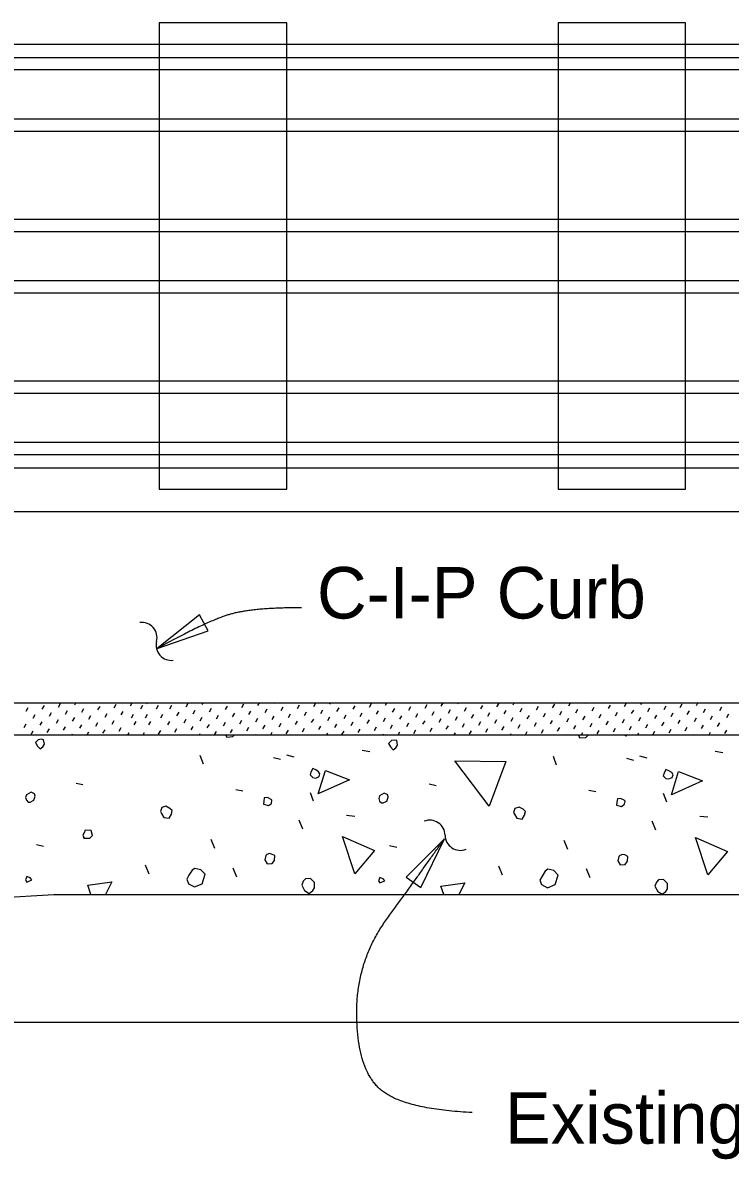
# Model space of a CAD drawing. Extents: x 1.5 to 68.7, y 0 to 31.1.
# Drawn here: x 31.375 to 34.147, y 9.197 to 13.648 of the extents above; entities that cross this region are included whole.
import ezdxf

# ---------------------------------------------------------------- set-up
doc = ezdxf.new("R2010")
doc.units = 0
for name, color, linetype in [('Dimension', 7, 'Continuous'), ('Miscellaneous', 7, 'Continuous'), ('TextStructures', 7, 'Continuous'), ('TrafBarrierConc', 7, 'Continuous')]:
    doc.layers.add(name, color=color, linetype=linetype)

msp = doc.modelspace()

# ---------------------------------------------------------------- linework, layer by layer
at = {"layer": 'Dimension'}
for points in [[(31.9014, 11.1976), (32.1009, 11.2667), (32.067, 11.3286)], [(33.0264, 10.4517), (32.8772, 10.3022), (32.9348, 10.2614)]]:
    msp.add_lwpolyline(points, close=True, dxfattribs=at)
for centre, start, end in [((31.8414, 11.2396), 345.7563, 97.4835), ((31.9569, 11.2103), 165.7563, 277.4835), ((32.9696, 10.4655), 0.5042, 112.2314), ((33.0889, 10.4666), 180.5042, 292.2314)]:
    msp.add_arc(centre, 0.0596, start, end, dxfattribs=at)
for points in [[(32.467, 11.357), (32.2731, 11.357), (32.0952, 11.3038), (31.9014, 11.1976)], [(33.1354, 9.3803), (32.866, 9.3932), (32.6865, 9.5471), (32.68, 9.9706), (32.9173, 10.2978), (33.0264, 10.4518)]]:
    msp.add_open_spline(points, degree=2, dxfattribs=at)
at = {"layer": 'Miscellaneous'}
for p, q in [((28.9195, 13.5645), (37.6978, 13.5645)), ((29.5771, 13.5123), (37.6978, 13.5123)), ((29.5783, 13.4641), (37.6978, 13.4641)), ((29.5831, 13.2713), (37.6978, 13.2713)), ((29.5842, 13.2231), (37.6978, 13.2231)), ((29.5807, 12.8791), (37.6978, 12.8791)), ((29.5795, 12.8309), (37.6978, 12.8309)), ((29.5747, 12.6381), (37.6978, 12.6381)), ((29.5735, 12.5899), (37.6978, 12.5899)), ((29.5842, 12.246), (37.6978, 12.246)), ((29.5831, 12.1978), (37.6978, 12.1978)), ((29.5783, 12.0049), (37.6978, 12.0049)), ((29.5771, 11.9567), (37.6978, 11.9567)), ((28.9195, 11.9044), (37.6978, 11.9044)), ((31.3878, 10.952), (31.3959, 10.966)), ((31.4513, 10.9601), (31.4594, 10.9741)), ((31.5148, 10.9682), (31.5229, 10.9822)), ((31.5425, 10.9405), (31.5506, 10.9545)), ((31.5783, 10.9763), (31.583, 10.9845)), ((31.606, 10.9486), (31.6141, 10.9626)), ((31.6418, 10.9844), (31.6418, 10.9845)), ((31.6695, 10.9567), (31.6776, 10.9707)), ((31.733, 10.9648), (31.7411, 10.9788)), ((31.7607, 10.9371), (31.7688, 10.9511)), ((31.7964, 10.9729), (31.8032, 10.9845)), ((31.8376, 10.9614), (31.8457, 10.9754)), ((31.8599, 10.981), (31.862, 10.9845)), ((31.8986, 10.9614), (31.9067, 10.9754)), ((31.9511, 10.9614), (31.9592, 10.9754)), ((32.0146, 10.9695), (32.0227, 10.9835)), ((32.0423, 10.9418), (32.0504, 10.9558)), ((32.0781, 10.9776), (32.0821, 10.9845)), ((32.1058, 10.9499), (32.1139, 10.9639)), ((32.1693, 10.958), (32.1774, 10.972)), ((32.2328, 10.9661), (32.2409, 10.9801)), ((32.2605, 10.9384), (32.2686, 10.9524)), ((32.2963, 10.9742), (32.3022, 10.9845)), ((32.324, 10.9465), (32.3321, 10.9605)), ((32.3598, 10.9823), (32.361, 10.9845)), ((32.3875, 10.9546), (32.3956, 10.9686)), ((32.451, 10.9627), (32.4591, 10.9767)), ((32.4787, 10.935), (32.4868, 10.949)), ((32.5145, 10.9708), (32.5224, 10.9845)), ((32.5422, 10.9431), (32.5503, 10.9571)), ((32.578, 10.9789), (32.5812, 10.9845)), ((32.6056, 10.9512), (32.6137, 10.9652)), ((32.6691, 10.9593), (32.6772, 10.9733)), ((32.7326, 10.9674), (32.7407, 10.9814)), ((32.7603, 10.9397), (32.7684, 10.9537)), ((32.7961, 10.9755), (32.8013, 10.9845)), ((32.8238, 10.9479), (32.8319, 10.9618)), ((32.8596, 10.9836), (32.8601, 10.9845)), ((32.8873, 10.956), (32.8954, 10.9699)), ((32.9508, 10.9641), (32.9589, 10.978)), ((32.9785, 10.9364), (32.9866, 10.9504)), ((33.0143, 10.9722), (33.0214, 10.9845)), ((33.042, 10.9445), (33.0501, 10.9585)), ((33.0778, 10.9803), (33.0802, 10.9845)), ((33.1055, 10.9526), (33.1136, 10.9666)), ((33.169, 10.9607), (33.1771, 10.9747)), ((33.2325, 10.9688), (33.2406, 10.9828)), ((33.2602, 10.9411), (33.2683, 10.9551)), ((33.296, 10.9769), (33.3004, 10.9845)), ((33.3237, 10.9492), (33.3318, 10.9632)), ((33.3871, 10.9573), (33.3952, 10.9713)), ((33.4506, 10.9654), (33.4587, 10.9794)), ((33.4783, 10.9377), (33.4864, 10.9517)), ((33.5141, 10.9735), (33.5205, 10.9845)), ((33.5418, 10.9458), (33.5499, 10.9598)), ((33.5776, 10.9816), (33.5793, 10.9845)), ((33.6053, 10.9539), (33.6134, 10.9679)), ((33.6688, 10.962), (33.6769, 10.976)), ((33.7323, 10.9701), (33.7404, 10.9841)), ((33.76, 10.9424), (33.7681, 10.9564)), ((33.7958, 10.9782), (33.7994, 10.9845)), ((33.8235, 10.9505), (33.8316, 10.9645)), ((33.887, 10.9586), (33.8951, 10.9726)), ((33.9505, 10.9667), (33.9586, 10.9807)), ((33.9782, 10.939), (33.9863, 10.953)), ((34.014, 10.9748), (34.0196, 10.9845)), ((34.0417, 10.9471), (34.0498, 10.9611)), ((34.0775, 10.9829), (34.0784, 10.9845)), ((34.1052, 10.9552), (34.1133, 10.9692)), ((31.4155, 10.9243), (31.4236, 10.9383)), ((31.4432, 10.8966), (31.4513, 10.9106)), ((31.479, 10.9324), (31.4871, 10.9464)), ((31.5067, 10.9047), (31.5148, 10.9187)), ((31.5702, 10.9128), (31.5783, 10.9268)), ((31.6337, 10.9209), (31.6418, 10.9349)), ((31.6614, 10.8932), (31.6695, 10.9072)), ((31.6972, 10.929), (31.7053, 10.943)), ((31.7249, 10.9013), (31.733, 10.9153)), ((31.8002, 10.9256), (31.8083, 10.9396)), ((31.8109, 10.8979), (31.8191, 10.9119)), ((31.856, 10.9256), (31.8641, 10.9396)), ((31.8681, 10.8979), (31.8762, 10.9119)), ((31.9153, 10.9256), (31.9234, 10.9396)), ((31.943, 10.8979), (31.9511, 10.9119)), ((31.9788, 10.9337), (31.9869, 10.9477)), ((32.0065, 10.906), (32.0146, 10.92)), ((32.07, 10.9141), (32.0781, 10.9281)), ((32.1335, 10.9222), (32.1416, 10.9362)), ((32.1612, 10.8945), (32.1693, 10.9085)), ((32.197, 10.9303), (32.2051, 10.9443)), ((32.2247, 10.9026), (32.2328, 10.9166)), ((32.2882, 10.9107), (32.2963, 10.9247)), ((32.3517, 10.9188), (32.3598, 10.9328)), ((32.3794, 10.8911), (32.3875, 10.9051)), ((32.4152, 10.9269), (32.4233, 10.9409)), ((32.4429, 10.8992), (32.451, 10.9132)), ((32.5064, 10.9073), (32.5145, 10.9213)), ((32.5698, 10.9154), (32.578, 10.9294)), ((32.6333, 10.9235), (32.6414, 10.9375)), ((32.661, 10.8958), (32.6691, 10.9098)), ((32.6968, 10.9316), (32.7049, 10.9456)), ((32.7245, 10.904), (32.7326, 10.9179)), ((32.788, 10.9121), (32.7961, 10.926)), ((32.8515, 10.9202), (32.8596, 10.9342)), ((32.8792, 10.8925), (32.8873, 10.9065)), ((32.915, 10.9283), (32.9231, 10.9423)), ((32.9427, 10.9006), (32.9508, 10.9146)), ((33.0062, 10.9087), (33.0143, 10.9227)), ((33.0697, 10.9168), (33.0778, 10.9308)), ((33.1332, 10.9249), (33.1413, 10.9389)), ((33.1609, 10.8972), (33.169, 10.9112)), ((33.1967, 10.933), (33.2048, 10.947)), ((33.2244, 10.9053), (33.2325, 10.9193)), ((33.2879, 10.9134), (33.296, 10.9274)), ((33.3513, 10.9215), (33.3595, 10.9355)), ((33.379, 10.8938), (33.3871, 10.9078)), ((33.4148, 10.9296), (33.4229, 10.9436)), ((33.4425, 10.9019), (33.4506, 10.9159)), ((33.506, 10.91), (33.5141, 10.924)), ((33.5695, 10.9181), (33.5776, 10.9321)), ((33.5972, 10.8904), (33.6053, 10.9044)), ((33.633, 10.9262), (33.6411, 10.9402)), ((33.6607, 10.8985), (33.6688, 10.9125)), ((33.6965, 10.9343), (33.7046, 10.9483)), ((33.7242, 10.9066), (33.7323, 10.9206)), ((33.7877, 10.9147), (33.7958, 10.9287)), ((33.8512, 10.9228), (33.8593, 10.9368)), ((33.8789, 10.8951), (33.887, 10.9091)), ((33.9147, 10.9309), (33.9228, 10.9449)), ((33.9424, 10.9032), (33.9505, 10.9172)), ((34.0059, 10.9113), (34.014, 10.9253)), ((34.0694, 10.9194), (34.0775, 10.9334)), ((34.0971, 10.8917), (34.1052, 10.9057)), ((34.1328, 10.9275), (34.141, 10.9415)), ((31.3797, 10.8885), (31.3878, 10.9025)), ((31.4074, 10.8608), (31.4155, 10.8748)), ((31.4709, 10.8689), (31.479, 10.8829)), ((31.5344, 10.877), (31.5425, 10.891)), ((31.568, 10.8595), (31.5702, 10.8633)), ((31.5979, 10.8851), (31.606, 10.8991)), ((31.6268, 10.8595), (31.6337, 10.8714)), ((31.6891, 10.8655), (31.6972, 10.8795)), ((31.7526, 10.8736), (31.7607, 10.8876)), ((31.7865, 10.8595), (31.7914, 10.868)), ((31.7881, 10.8595), (31.7883, 10.8599)), ((31.8469, 10.8595), (31.8518, 10.868)), ((31.9072, 10.8621), (31.9153, 10.8761)), ((31.9707, 10.8702), (31.9788, 10.8842)), ((32.0342, 10.8783), (32.0423, 10.8923)), ((32.067, 10.8595), (32.07, 10.8646)), ((32.0977, 10.8864), (32.1058, 10.9004)), ((32.1258, 10.8595), (32.1335, 10.8727)), ((32.1889, 10.8668), (32.197, 10.8808)), ((32.2524, 10.8749), (32.2605, 10.8889)), ((32.2872, 10.8595), (32.2882, 10.8612)), ((32.3159, 10.883), (32.324, 10.897)), ((32.346, 10.8595), (32.3517, 10.8693)), ((32.4071, 10.8634), (32.4152, 10.8774)), ((32.4706, 10.8715), (32.4787, 10.8855)), ((32.5341, 10.8796), (32.5422, 10.8936)), ((32.5661, 10.8595), (32.5698, 10.8659)), ((32.5975, 10.8877), (32.6056, 10.9017)), ((32.6252, 10.8601), (32.6333, 10.874)), ((32.6887, 10.8682), (32.6968, 10.8821)), ((32.7522, 10.8763), (32.7603, 10.8903)), ((32.7862, 10.8595), (32.788, 10.8626)), ((32.8157, 10.8844), (32.8238, 10.8984)), ((32.845, 10.8595), (32.8515, 10.8707)), ((32.9069, 10.8648), (32.915, 10.8788)), ((32.9704, 10.8729), (32.9785, 10.8869)), ((33.0339, 10.881), (33.042, 10.895)), ((33.0652, 10.8595), (33.0697, 10.8673)), ((33.0974, 10.8891), (33.1055, 10.9031)), ((33.1251, 10.8614), (33.1332, 10.8754)), ((33.1886, 10.8695), (33.1967, 10.8835)), ((33.2521, 10.8776), (33.2602, 10.8916)), ((33.2853, 10.8595), (33.2879, 10.8639)), ((33.3156, 10.8857), (33.3237, 10.8997)), ((33.3441, 10.8595), (33.3513, 10.872)), ((33.4067, 10.8661), (33.4148, 10.8801)), ((33.4702, 10.8742), (33.4783, 10.8882)), ((33.5054, 10.8595), (33.506, 10.8605)), ((33.5337, 10.8823), (33.5418, 10.8963)), ((33.5642, 10.8595), (33.5695, 10.8686)), ((33.6249, 10.8627), (33.633, 10.8767)), ((33.6884, 10.8708), (33.6965, 10.8848)), ((33.7519, 10.8789), (33.76, 10.8929)), ((33.7844, 10.8595), (33.7877, 10.8652)), ((33.8154, 10.887), (33.8235, 10.901)), ((33.8432, 10.8595), (33.8512, 10.8733)), ((33.9066, 10.8674), (33.9147, 10.8814)), ((33.9701, 10.8755), (33.9782, 10.8895)), ((34.0045, 10.8595), (34.0059, 10.8618)), ((34.0336, 10.8836), (34.0417, 10.8976)), ((34.0633, 10.8595), (34.0694, 10.8699)), ((34.1247, 10.864), (34.1328, 10.878)), ((32.0825, 10.7446), (32.0701, 10.7782)), ((32.3565, 10.7711), (32.3848, 10.764)), ((32.4082, 10.7804), (32.4365, 10.7733)), ((32.7038, 10.7994), (32.7339, 10.7941)), ((33.4657, 10.741), (33.4534, 10.7746)), ((33.7915, 10.7768), (33.8197, 10.7698)), ((34.0871, 10.7958), (34.1172, 10.7905)), ((33.7397, 10.7676), (33.768, 10.7605)), ((31.584, 10.6703), (31.6105, 10.665)), ((32.2097, 10.6456), (32.2363, 10.6403)), ((32.9672, 10.6668), (32.9937, 10.6615)), ((33.593, 10.6421), (33.6195, 10.6368)), ((32.5142, 10.5992), (32.5019, 10.6328)), ((33.8975, 10.5957), (33.8851, 10.6292)), ((32.4718, 10.4896), (32.4577, 10.5249)), ((32.6437, 10.5448), (32.6755, 10.5413)), ((33.8551, 10.486), (33.8409, 10.5214)), ((34.027, 10.5413), (34.0588, 10.5378)), ((31.4284, 10.4299), (31.4567, 10.4229)), ((32.1267, 10.414), (32.1125, 10.4494)), ((32.8117, 10.4264), (32.84, 10.4193)), ((33.5099, 10.4105), (33.4958, 10.4458)), ((31.8703, 10.3132), (31.8562, 10.3486)), ((32.2137, 10.3022), (32.1996, 10.3376)), ((33.2536, 10.3097), (33.2395, 10.3451)), ((33.597, 10.2987), (33.5829, 10.334))]:
    msp.add_line(p, q, dxfattribs=at)
for points in [[(31.9092, 11.8211), (32.4092, 11.8211), (32.4092, 13.6478), (31.9092, 13.6478)], [(33.4717, 11.8211), (33.9717, 11.8211), (33.9717, 13.6478), (33.4717, 13.6478)]]:
    msp.add_lwpolyline(points, close=True, dxfattribs=at)
for points in [[(32.169, 10.8594), (32.1744, 10.8507), (32.1974, 10.8524), (32.2044, 10.8594)], [(33.5501, 10.8594), (33.5577, 10.8471), (33.5806, 10.8489), (33.5895, 10.8577), (33.5912, 10.8594)], [(33.7367, 10.8529), (33.7345, 10.8594)], [(33.74, 10.8594), (33.7367, 10.8529)], [(31.4319, 10.8153), (31.4425, 10.8047), (31.4531, 10.8118), (31.4602, 10.8224), (31.4567, 10.84), (31.4478, 10.8418), (31.4355, 10.84), (31.4249, 10.8294), (31.4319, 10.8153)], [(32.8152, 10.8118), (32.8258, 10.8012), (32.8364, 10.8082), (32.8435, 10.8188), (32.84, 10.8365), (32.8311, 10.8383), (32.8187, 10.8365), (32.8081, 10.8259), (32.8152, 10.8118)], [(32.5107, 10.692), (32.5231, 10.6902), (32.5355, 10.6955), (32.539, 10.7061), (32.5337, 10.715), (32.5231, 10.722), (32.5107, 10.7273), (32.5036, 10.7132), (32.5001, 10.7026), (32.5107, 10.692)], [(33.2023, 10.5802), (33.068, 10.757), (33.2678, 10.7552), (33.2023, 10.5802)], [(32.5324, 10.6279), (32.5606, 10.7198), (32.6543, 10.6827), (32.5324, 10.6279)], [(33.894, 10.6885), (33.9064, 10.6867), (33.9187, 10.692), (33.9223, 10.7026), (33.917, 10.7114), (33.9064, 10.7185), (33.894, 10.7238), (33.8869, 10.7097), (33.8834, 10.6991), (33.894, 10.6885)], [(33.9156, 10.6244), (33.9439, 10.7163), (34.0376, 10.6792), (33.9156, 10.6244)], [(31.3966, 10.5961), (31.4036, 10.5961), (31.4178, 10.6032), (31.4231, 10.6191), (31.4213, 10.6279), (31.4072, 10.635), (31.3895, 10.6244), (31.386, 10.6138), (31.3895, 10.6032), (31.3966, 10.5961)], [(32.3176, 10.5873), (32.337, 10.582), (32.3494, 10.5908), (32.3512, 10.6032), (32.3476, 10.6067), (32.3335, 10.6138), (32.3211, 10.612), (32.3193, 10.5996), (32.3176, 10.5873)], [(32.7798, 10.5926), (32.7869, 10.5926), (32.8011, 10.5996), (32.8064, 10.6155), (32.8046, 10.6244), (32.7905, 10.6314), (32.7728, 10.6208), (32.7692, 10.6102), (32.7728, 10.5996), (32.7798, 10.5926)], [(33.7009, 10.5837), (33.7203, 10.5784), (33.7327, 10.5873), (33.7344, 10.5996), (33.7309, 10.6032), (33.7168, 10.6102), (33.7044, 10.6085), (33.7026, 10.5961), (33.7009, 10.5837)], [(31.9181, 10.5519), (31.9269, 10.536), (31.9481, 10.5325), (31.957, 10.5484), (31.9605, 10.5625), (31.9516, 10.5713), (31.9357, 10.5802), (31.9198, 10.5749), (31.9145, 10.559), (31.9181, 10.5519)], [(33.3013, 10.5484), (33.3102, 10.5325), (33.3314, 10.5289), (33.3402, 10.5448), (33.3438, 10.559), (33.3349, 10.5678), (33.319, 10.5766), (33.3031, 10.5713), (33.2978, 10.5554), (33.3013, 10.5484)], [(31.6158, 10.4547), (31.637, 10.4547), (31.6476, 10.4653), (31.6423, 10.4847), (31.6193, 10.4865), (31.6158, 10.4759), (31.6105, 10.467), (31.6158, 10.4547), (31.6122, 10.4582)], [(32.6751, 10.3146), (32.6274, 10.4613), (32.7529, 10.4065), (32.6751, 10.3146)], [(34.0584, 10.311), (34.0107, 10.4578), (34.1362, 10.403), (34.0584, 10.311)], [(32.3233, 10.3694), (32.3322, 10.3535), (32.3516, 10.3552), (32.3604, 10.3676), (32.3622, 10.3871), (32.3498, 10.3924), (32.341, 10.3941), (32.3304, 10.3906), (32.3269, 10.3871), (32.3233, 10.3694)], [(33.7066, 10.3658), (33.7154, 10.3499), (33.7349, 10.3517), (33.7437, 10.3641), (33.7455, 10.3835), (33.7331, 10.3888), (33.7243, 10.3906), (33.7137, 10.3871), (33.7101, 10.3835), (33.7066, 10.3658)], [(32.0241, 10.2761), (32.0471, 10.2638), (32.0772, 10.2761), (32.0895, 10.3132), (32.0719, 10.3309), (32.0489, 10.3362), (32.0383, 10.3292), (32.0259, 10.3097), (32.0171, 10.2938), (32.0241, 10.2761)], [(33.4074, 10.2726), (33.4304, 10.2602), (33.4604, 10.2726), (33.4728, 10.3097), (33.4551, 10.3274), (33.4322, 10.3327), (33.4215, 10.3256), (33.4092, 10.3062), (33.4003, 10.2903), (33.4074, 10.2726)], [(31.3908, 10.2828), (31.4103, 10.2916), (31.4032, 10.2987), (31.3908, 10.304), (31.3855, 10.2916), (31.3908, 10.2828)], [(31.6416, 10.2344), (31.6299, 10.2708), (31.7236, 10.2832), (31.6985, 10.2344)], [(32.4683, 10.2704), (32.4789, 10.2492), (32.4966, 10.2386), (32.5107, 10.2492), (32.5178, 10.2598), (32.5178, 10.281), (32.5019, 10.2969), (32.4824, 10.2951), (32.4736, 10.2863), (32.4683, 10.2704)], [(32.7741, 10.2792), (32.7935, 10.2881), (32.7865, 10.2951), (32.7741, 10.3004), (32.7688, 10.2881), (32.7741, 10.2792)], [(33.8516, 10.2668), (33.8622, 10.2456), (33.8798, 10.235), (33.894, 10.2456), (33.9011, 10.2562), (33.9011, 10.2775), (33.8851, 10.2934), (33.8657, 10.2916), (33.8569, 10.2828), (33.8516, 10.2668)], [(33.0238, 10.2344), (33.0132, 10.2673), (33.1069, 10.2797), (33.0836, 10.2344)], [(31.4997, 10.2344), (31.4987, 10.235), (31.4972, 10.2344)]]:
    msp.add_lwpolyline(points, dxfattribs=at)
at = {"layer": 'TrafBarrierConc'}
for p, q in [((26.2771, 11.7345), (36.6763, 11.7345)), ((27.4971, 10.9845), (37.6978, 10.9845)), ((28.2772, 10.8595), (34.2217, 10.8595)), ((27.4971, 9.9844), (31.4971, 10.2344)), ((31.4971, 10.2345), (37.6978, 10.2345)), ((27.4971, 9.7345), (36.6763, 9.7345))]:
    msp.add_line(p, q, dxfattribs=at)

# ---------------------------------------------------------------- texts
at = {"layer": 'TextStructures'}
for s, p in [('C-I-P Curb', (32.5274, 11.3149)), ('Existing Approach Slab', (33.2635, 9.2581))]:
    msp.add_text(s, height=0.2016, dxfattribs=at).set_placement(p)

doc.saveas('drawing.dxf')
